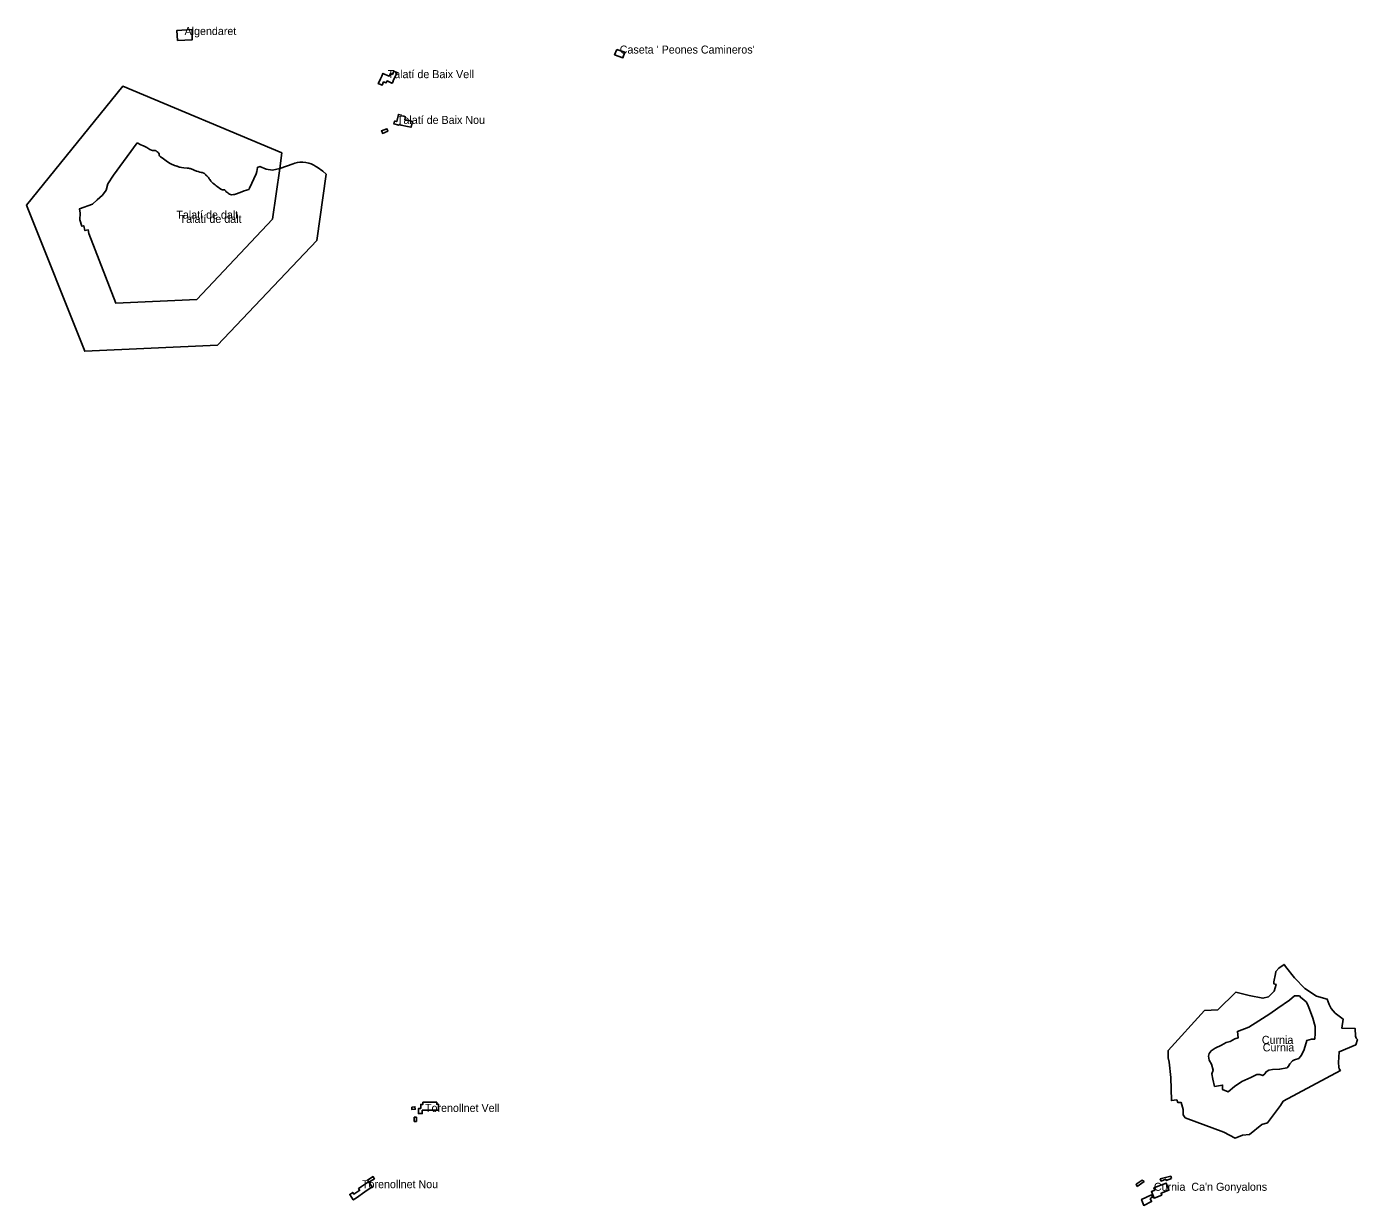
# Model space of a CAD drawing. Extents: x 599451 to 612034, y 4411179 to 4428219.
# Drawn here: x 603669 to 605665, y 4415101 to 4416870 of the extents above; entities that cross this region are included whole.
import ezdxf

# ---------------------------------------------------------------- set-up
doc = ezdxf.new("R2010")
doc.units = 0
for name, color, linetype in [('Bé Arquitectònic', 7, 'Continuous'), ('Elements patrimonials', 7, 'Continuous'), ('Muralla_ Perímetre de Protecció', 7, 'Continuous')]:
    doc.layers.add(name, color=color, linetype=linetype)

msp = doc.modelspace()

# ---------------------------------------------------------------- linework, layer by layer
at = {"layer": 'Bé Arquitectònic'}
for points in [[(603895.2, 4416848.8), (603917.1, 4416849.9), (603916.9, 4416865), (603894.1, 4416863.9)], [(604554.2, 4416835.4), (604550.6, 4416827.3), (604563.1, 4416822.7), (604566.1, 4416831)], [(604199.5, 4416791.3), (604199.3, 4416790.9), (604196.2, 4416784.1), (604201.8, 4416781.6), (604204.2, 4416786.6), (604207.8, 4416785), (604209.3, 4416788.1), (604216.7, 4416784.7), (604216.9, 4416784.6), (604218.3, 4416787.4), (604218.7, 4416788.3), (604220.1, 4416791.5), (604224.4, 4416800.7), (604224.2, 4416800.8), (604219.7, 4416802.9), (604217.4, 4416797.9), (604214.3, 4416799.3), (604212.4, 4416795.1), (604203.2, 4416799.3), (604201.3, 4416795.1)], [(604236.4, 4416732.5), (604236.5, 4416732.9), (604236.8, 4416734.4), (604234.4, 4416735), (604230.6, 4416735.8), (604230.8, 4416736.7), (604226.4, 4416737.8), (604223.9, 4416727.1), (604221.9, 4416727.6), (604220.6, 4416727.9), (604219.6, 4416723.5), (604227.2, 4416721.7), (604227.3, 4416721.7), (604227.3, 4416721.7), (604227.5, 4416722.6), (604227.6, 4416722.6), (604228, 4416722.5), (604230.5, 4416721.9), (604239.8, 4416719.8), (604245.4, 4416718.5), (604247.4, 4416727.3), (604241.8, 4416728.5), (604235.8, 4416729.9)], [(604201.8, 4416711), (604202.4, 4416709.4), (604206, 4416710.8), (604210.5, 4416712.6), (604209.9, 4416714.1), (604209.1, 4416716.3), (604201, 4416713)], [(604269.5, 4415255.8), (604263.2, 4415255.8), (604263.2, 4415252.7), (604260, 4415252.7), (604260, 4415246.7), (604256.6, 4415246.7), (604256.6, 4415243.9), (604256.4, 4415243.9), (604256.4, 4415238.8), (604262.2, 4415238.8), (604262.2, 4415243.9), (604269.6, 4415243.9), (604284.1, 4415243.9), (604286.3, 4415243.9), (604286.3, 4415253), (604284, 4415253), (604284, 4415255.8)], [(604246.3, 4415248.5), (604246.7, 4415244.9), (604251.6, 4415245.5), (604251.1, 4415249.1)], [(604252.3, 4415227.1), (604253.5, 4415227.1), (604253.5, 4415232.1), (604253.5, 4415233.5), (604250.2, 4415233.5), (604250.2, 4415227.1)], [(604170.9, 4415129.3), (604167.6, 4415127), (604166.6, 4415126.3), (604168.1, 4415124.1), (604168.3, 4415123.9), (604159.7, 4415118), (604157.9, 4415120.7), (604153.3, 4415117.6), (604158.7, 4415109.5), (604163.4, 4415112.6), (604176.2, 4415121.4), (604187, 4415128.8), (604182.1, 4415136), (604190.4, 4415141.2), (604189.1, 4415143.2), (604188.3, 4415144.4), (604180.1, 4415139.1), (604180, 4415139.1), (604180.3, 4415138.5), (604181, 4415137.4), (604181.6, 4415136.6)], [(605334.3, 4415129.6), (605344.9, 4415137.1), (605341.8, 4415138.9), (605333.1, 4415132.9)], [(605357.4, 4415122.5), (605355.9, 4415121.9), (605360, 4415111.9), (605361.4, 4415112.5), (605370, 4415115.9), (605371.5, 4415116.6), (605370.4, 4415119.3), (605382.1, 4415124), (605377.9, 4415134.6), (605359.7, 4415127.3), (605361, 4415124)], [(605386.1, 4415141.4), (605385, 4415145), (605369.1, 4415140.8), (605370.3, 4415137.7), (605377.4, 4415140.4), (605378.2, 4415138.3)], [(605354, 4415111.6), (605357.7, 4415113.3), (605356, 4415117), (605341.2, 4415110.1), (605342.5, 4415106.2), (605344.3, 4415101.2), (605356.2, 4415106.8)]]:
    msp.add_lwpolyline(points, close=True, dxfattribs=at)
at = {"layer": 'Elements patrimonials'}
for points in [[(603834.4, 4416695.3), (603799.1, 4416646.6), (603790.5, 4416633.5), (603788, 4416624.3), (603782.7, 4416616.9), (603774.6, 4416609.8), (603767.4, 4416603.3), (603748.2, 4416596.3), (603748.9, 4416589.6), (603748.3, 4416579.7), (603751.6, 4416570.1), (603754.4, 4416570.7), (603756.1, 4416563.5), (603761.2, 4416564.6), (603762.2, 4416559.1), (603802.5, 4416454.9), (603923.8, 4416460.4), (604037.7, 4416580.8), (604048.3, 4416656.7), (604037.3, 4416654.4), (604028, 4416655.5), (604018.3, 4416659.6), (604014.9, 4416658.2), (604013.8, 4416652.1), (604012.8, 4416648.5), (604002.8, 4416627.2), (604002, 4416625.2), (603994.8, 4416623.1), (603989.2, 4416620.9), (603981.8, 4416618.3), (603980.3, 4416617.8), (603979, 4416617.5), (603976.1, 4416617.1), (603975.2, 4416617.4), (603973.8, 4416618), (603973, 4416618.4), (603971.4, 4416619.3), (603970.3, 4416620), (603968.9, 4416621.1), (603968.2, 4416621.6), (603967.3, 4416622.7), (603966.8, 4416623.4), (603966.1, 4416624.3), (603965.8, 4416624.6), (603965.3, 4416624.8), (603964.7, 4416624.9), (603962.3, 4416624.9), (603960.9, 4416625.2), (603960.4, 4416625.5), (603959.9, 4416625.7), (603957.8, 4416627), (603956.4, 4416628.1), (603954.4, 4416629.5), (603952.8, 4416630.8), (603951.8, 4416631.8), (603951.3, 4416632.2), (603950.2, 4416633.1), (603949.3, 4416633.7), (603948.1, 4416634.7), (603947.5, 4416635.2), (603946.6, 4416636.1), (603946.1, 4416636.7), (603945.2, 4416637.8), (603944.6, 4416638.5), (603943.5, 4416640.2), (603942.6, 4416641.4), (603941.5, 4416643), (603941, 4416643.6), (603940.4, 4416644.2), (603940.1, 4416644.5), (603939.4, 4416645.1), (603938.9, 4416645.6), (603937.7, 4416646.9), (603936.8, 4416647.9), (603935.3, 4416649.3), (603934.8, 4416649.6), (603934.3, 4416649.8), (603932.2, 4416650.5), (603930.7, 4416650.8), (603928.6, 4416651.3), (603926.2, 4416652), (603923.7, 4416652.9), (603915.4, 4416656.1), (603914.2, 4416656.5), (603913.5, 4416656.7), (603912.6, 4416656.9), (603911.8, 4416657), (603909.6, 4416657.2), (603904.5, 4416657.7), (603900.9, 4416658.2), (603899.1, 4416658.6), (603898.2, 4416658.8), (603896.7, 4416659.3), (603895.7, 4416659.7), (603894.4, 4416660.2), (603893.8, 4416660.4), (603892.5, 4416660.8), (603890.7, 4416661.4), (603885.1, 4416663.8), (603883.9, 4416664.3), (603883.1, 4416664.7), (603878.1, 4416668), (603872.1, 4416672.6), (603869.5, 4416674.3), (603868.3, 4416675.3), (603867.9, 4416675.9), (603867.7, 4416676.5), (603867.6, 4416677.1), (603867.6, 4416677.5), (603867.6, 4416677.9), (603867.5, 4416678.5), (603867.4, 4416679), (603867.2, 4416679.4), (603866.5, 4416680.2), (603865.5, 4416681.1), (603864.6, 4416681.9), (603864, 4416682.3), (603863.4, 4416682.9), (603863, 4416683.1), (603862.7, 4416683.3), (603862.4, 4416683.4), (603861.8, 4416683.5), (603860.2, 4416683.6), (603859, 4416683.6), (603857, 4416683.9), (603856.5, 4416684.1), (603855.9, 4416684.3), (603853.6, 4416685.4), (603849.2, 4416688), (603847.8, 4416688.8), (603846.8, 4416689.3), (603845.9, 4416689.7), (603843.8, 4416690.6), (603842.3, 4416691.2), (603840, 4416692)], [(605445.7, 4415333.3), (605442.3, 4415329.3), (605441.4, 4415325.1), (605442.7, 4415319.3), (605446.2, 4415313.1), (605448.5, 4415304.1), (605446.4, 4415298.4), (605448.2, 4415290.4), (605450.7, 4415279.6), (605462.6, 4415281.7), (605462.7, 4415274.8), (605470.8, 4415271.6), (605480.4, 4415279.5), (605491.5, 4415286.9), (605504.9, 4415293.2), (605514.1, 4415297.4), (605518.3, 4415297.4), (605522.8, 4415295.9), (605525.9, 4415298.4), (605527.8, 4415301.6), (605531.9, 4415304), (605537.4, 4415305), (605548.1, 4415305.4), (605559.4, 4415307.4), (605561.6, 4415310), (605563.5, 4415313.8), (605567.7, 4415317.9), (605570.7, 4415319.7), (605577, 4415321.8), (605581.1, 4415326.8), (605585, 4415335.1), (605589.2, 4415348.8), (605595.9, 4415350.6), (605596.6, 4415350.8), (605600.8, 4415350.6), (605601.6, 4415359.6), (605601.5, 4415369.6), (605597.8, 4415382.2), (605593, 4415395.6), (605591.2, 4415400.6), (605588.3, 4415406.2), (605584.5, 4415409.8), (605579.8, 4415413), (605578, 4415415.4), (605570.4, 4415415.5), (605563, 4415409.2), (605545.3, 4415396.9), (605533.6, 4415388.8), (605517.2, 4415378.2), (605502, 4415368.4), (605484.8, 4415362.2), (605486.1, 4415352.6), (605481, 4415351.2), (605473.9, 4415347.2), (605467.8, 4415345.7), (605461.1, 4415341.6), (605451.5, 4415336.9)]]:
    msp.add_lwpolyline(points, close=True, dxfattribs=at)
at = {"layer": 'Muralla_ Perímetre de Protecció'}
for points in [[(604051.6, 4416680.3), (603813.1, 4416780.2), (603668.7, 4416601.8), (603755.9, 4416382.6), (603955.2, 4416391.8), (604104, 4416548.9), (604117.8, 4416648.2), (604113.2, 4416652.6), (604104.5, 4416658.6), (604102.6, 4416659.6), (604099.3, 4416661.5), (604095.3, 4416663.5), (604092, 4416664.8), (604087.4, 4416665.7), (604083.1, 4416666.3), (604078.5, 4416666.1), (604074.9, 4416665.7), (604071, 4416664.7), (604068.4, 4416663.8), (604048.3, 4416656.7)], [(605381.1, 4415333.5), (605381, 4415322.7), (605382.3, 4415316), (605385, 4415293.1), (605385.9, 4415258.5), (605394, 4415259.3), (605395.4, 4415255.6), (605400.7, 4415255.5), (605403.3, 4415245), (605403.5, 4415237.1), (605406.7, 4415232.4), (605464.7, 4415211), (605481.4, 4415201.8), (605492.3, 4415206.7), (605503.1, 4415207.5), (605521.4, 4415222.6), (605530.1, 4415224.8), (605549.4, 4415250.9), (605553.7, 4415257.4), (605639.3, 4415303.7), (605637.4, 4415305.9), (605637, 4415308.5), (605636.6, 4415315.5), (605637.5, 4415331.7), (605662.3, 4415342.1), (605664.8, 4415350.1), (605663.1, 4415352.1), (605662.1, 4415355.1), (605661.4, 4415366.6), (605641.4, 4415367.3), (605643.5, 4415380.6), (605631.3, 4415389.7), (605625.7, 4415396.5), (605622.5, 4415402.5), (605619.7, 4415410.5), (605603.4, 4415414.9), (605585.9, 4415426.8), (605570.4, 4415442.8), (605556.9, 4415459.6), (605554.8, 4415462.6), (605547.2, 4415457.1), (605542.7, 4415451.9), (605541.8, 4415448.7), (605539.4, 4415436.5), (605539.7, 4415433.6), (605543, 4415432.6), (605541.4, 4415427.6), (605540.2, 4415422.4), (605531.4, 4415414), (605523.2, 4415412), (605502.3, 4415416.3), (605482.7, 4415420.9), (605455.3, 4415394.6), (605435.7, 4415393.8)]]:
    msp.add_lwpolyline(points, close=True, dxfattribs=at)

# ---------------------------------------------------------------- texts
at = {"layer": 'Bé Arquitectònic'}
for s, p in [('Algendaret', (603905.6, 4416856.9)), ("Caseta ' Peones Camineros'", (604558.4, 4416829.1)), ('Talatí de Baix Vell', (604210.3, 4416792.2)), ('Talatí de Baix Nou', (604224.2, 4416723.6)), ('Torenollnet Vell', (604266.3, 4415241.4)), ('Torenollnet Nou', (604171.8, 4415127)), ("Curnia  Ca'n Gonyalons", (605359.6, 4415123.1))]:
    msp.add_text(s, height=12, dxfattribs=at).set_placement(p)
at = {"layer": 'Elements patrimonials'}
for s, p in [('Talatí de dalt', (603898.3, 4416575.1)), ('Curnia', (605521.5, 4415343.5))]:
    msp.add_text(s, height=12, dxfattribs=at).set_placement(p)
at = {"layer": 'Muralla_ Perímetre de Protecció'}
for s, p in [('Talatí de dalt', (603893.3, 4416581.4)), ('Curnia', (605522.9, 4415332.2))]:
    msp.add_text(s, height=12, dxfattribs=at).set_placement(p)

doc.saveas('drawing.dxf')
